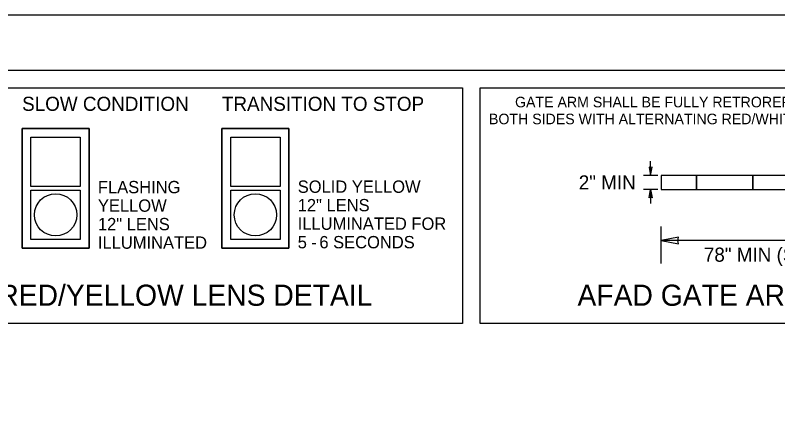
# Model space of a CAD drawing. Extents: x 99999.1 to 100095.7, y 99995 to 100010.7.
# Drawn here: x 100045 to 100049.325, y 100008.432 to 100010.687 of the extents above; entities that cross this region are included whole.
import ezdxf

# ---------------------------------------------------------------- set-up
doc = ezdxf.new("R2010")
doc.units = 0
for name, color, linetype in [('SH_GI_PlotLimits', 7, 'Continuous'), ('SH_GI_SheetBorder', 7, 'Continuous'), ('TR_WZ_WorkZoneDetails', 7, 'Continuous')]:
    doc.layers.add(name, color=color, linetype=linetype)

msp = doc.modelspace()

# ---------------------------------------------------------------- linework, layer by layer
at = {"layer": 'SH_GI_PlotLimits'}
msp.add_lwpolyline([(100039.0625, 99999.6875), (100056.0625, 99999.6875), (100056.0625, 100010.6875), (100039.0625, 100010.6875)], close=True, dxfattribs=at)
at = {"layer": 'SH_GI_SheetBorder'}
msp.add_line((100040, 100010.375), (100055.75, 100010.375), dxfattribs=at)
at = {"layer": 'TR_WZ_WorkZoneDetails'}
for p, q in [((100048.6043, 100009.779), (100048.6043, 100009.859)), ((100048.6443, 100009.779), (100048.5643, 100009.779)), ((100048.6443, 100009.699), (100048.5643, 100009.699)), ((100048.6043, 100009.699), (100048.6043, 100009.619)), ((100048.6643, 100009.279), (100048.6643, 100009.489)), ((100050.4643, 100009.409), (100048.6643, 100009.409))]:
    msp.add_line(p, q, dxfattribs=at)
for points in [[(100043.7984, 100009.1532), (100043.7984, 100010.275), (100047.5374, 100010.275), (100047.5374, 100008.939), (100044.2627, 100008.939)], [(100045.039, 100010.045), (100045.419, 100010.045), (100045.419, 100009.365), (100045.039, 100009.365), (100045.039, 100010.045)], [(100046.1723, 100010.045), (100046.5523, 100010.045), (100046.5523, 100009.365), (100046.1723, 100009.365), (100046.1723, 100010.045)], [(100045.089, 100009.995), (100045.369, 100009.995), (100045.369, 100009.715), (100045.089, 100009.715), (100045.089, 100009.995)], [(100046.2223, 100009.995), (100046.5023, 100009.995), (100046.5023, 100009.715), (100046.2223, 100009.715), (100046.2223, 100009.995)], [(100048.6643, 100009.699), (100048.8643, 100009.699), (100048.8643, 100009.779), (100048.6643, 100009.779), (100048.6643, 100009.699)], [(100050.4643, 100009.779), (100048.6643, 100009.779), (100048.6643, 100009.699), (100050.4643, 100009.699), (100050.4643, 100009.779)], [(100048.8643, 100009.699), (100049.1843, 100009.699), (100049.1843, 100009.779), (100048.8643, 100009.779), (100048.8643, 100009.699)], [(100049.1843, 100009.699), (100049.5043, 100009.699), (100049.5043, 100009.779), (100049.1843, 100009.779), (100049.1843, 100009.699)], [(100045.089, 100009.695), (100045.369, 100009.695), (100045.369, 100009.415), (100045.089, 100009.415), (100045.089, 100009.695)], [(100046.2223, 100009.695), (100046.5023, 100009.695), (100046.5023, 100009.415), (100046.2223, 100009.415), (100046.2223, 100009.695)]]:
    msp.add_lwpolyline(points, dxfattribs=at)
for points in [[(100047.6374, 100010.275), (100050.9639, 100010.275), (100050.9639, 100008.939), (100047.6374, 100008.939)], [(100045.419, 100010.045), (100045.039, 100010.045), (100045.039, 100009.365), (100045.419, 100009.365)], [(100046.5523, 100010.045), (100046.1723, 100010.045), (100046.1723, 100009.365), (100046.5523, 100009.365)], [(100045.089, 100009.995), (100045.369, 100009.995), (100045.369, 100009.715), (100045.089, 100009.715)], [(100046.2223, 100009.995), (100046.5023, 100009.995), (100046.5023, 100009.715), (100046.2223, 100009.715)], [(100048.6043, 100009.779), (100048.6136, 100009.8262), (100048.6043, 100009.824), (100048.5951, 100009.8262)], [(100045.089, 100009.695), (100045.369, 100009.695), (100045.369, 100009.415), (100045.089, 100009.415)], [(100046.2223, 100009.695), (100046.5023, 100009.695), (100046.5023, 100009.415), (100046.2223, 100009.415)], [(100048.6043, 100009.699), (100048.6136, 100009.6518), (100048.6043, 100009.654), (100048.5951, 100009.6518)], [(100048.6643, 100009.409), (100048.7626, 100009.3897), (100048.7581, 100009.409), (100048.7626, 100009.4283)]]:
    msp.add_lwpolyline(points, close=True, dxfattribs=at)
for centre in [(100045.229, 100009.555), (100046.3623, 100009.555)]:
    msp.add_circle(centre, 0.12, dxfattribs=at)

# ---------------------------------------------------------------- texts
for s, height, p in [('SLOW CONDITION', 0.08, (100045.039, 100010.145)), ('TRANSITION TO STOP', 0.08, (100046.1723, 100010.145)), ('GATE ARM SHALL BE FULLY RETROREFLECTIVE ON', 0.06, (100047.8352, 100010.165)), ('BOTH SIDES WITH ALTERNATING RED/WHITE SHEETING', 0.06, (100047.6874, 100010.069)), ('FLASHING', 0.07, (100045.469, 100009.6775)), ('SOLID YELLOW', 0.07, (100046.6023, 100009.68)), ('12" LENS ', 0.07, (100046.6023, 100009.575)), ('YELLOW', 0.07, (100045.469, 100009.5725)), ('12" LENS ', 0.07, (100045.469, 100009.4675)), ('ILLUMINATED FOR', 0.07, (100046.6023, 100009.47)), ('ILLUMINATED', 0.07, (100045.469, 100009.3625)), ('5', 0.07, (100046.6023, 100009.365)), ('6 SECONDS', 0.07, (100046.7251, 100009.365)), ('-', 0.07, (100046.6796, 100009.365)), ('78" MIN (SEE NOTE 13)', 0.08, (100048.9061, 100009.289))]:
    msp.add_text(s, height=height, dxfattribs=at).set_placement(p)
for s, height, p in [('2" MIN', 0.08, (100048.1966, 100009.699)), ('AFAD RED/YELLOW LENS DETAIL', 0.12, (100044.4311, 100009.039)), ('AFAD GATE ARM DETAIL', 0.12, (100048.1893, 100009.039))]:
    msp.add_text(s, height=height, rotation=360, dxfattribs=at).set_placement(p)

doc.saveas('drawing.dxf')
